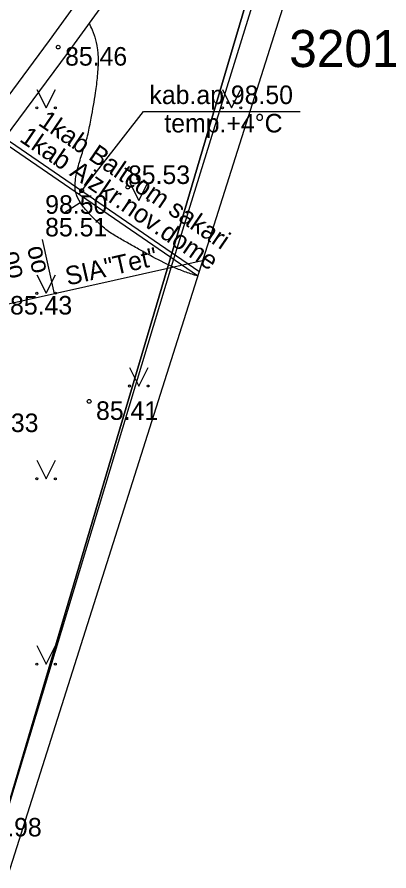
# Model space of a CAD drawing. Extents: x 576692 to 577659, y 273254 to 273799.
# Drawn here: x 576961.72 to 576971.74, y 273541.92 to 273564.95 of the extents above; entities that cross this region are included whole.
import ezdxf

# ---------------------------------------------------------------- set-up
doc = ezdxf.new("R2010")
doc.units = 0
for name, color, linetype in [('BUVE_BDET_####_####_#', 7, 'Continuous'), ('BUVE_EKAS_BPAL_####_#', 7, 'Continuous'), ('CELI_TAKA_####_####_#', 7, 'Continuous'), ('CKOM_ELEM_####_TKST_#', 7, 'Continuous'), ('ELEK_ELEM_####_####_#', 7, 'Continuous'), ('GAZE_VADP_VSP1_####_#', 7, 'Continuous'), ('GAZE_VADV_VSP1_TKST_#', 7, 'Continuous'), ('GEOD_SITP_####_TKST_#', 7, 'Continuous'), ('HIDT_REZV_####_TKST_#', 7, 'Continuous'), ('Level 62', 7, 'Continuous'), ('LKAN_ELEM_PAST_TKST_#', 7, 'Continuous'), ('POINT-ELEV', 7, 'Continuous'), ('RELJ_ELEM_####_####_#', 7, 'Continuous'), ('SILT_VADP_UDEN_####_#', 7, 'Continuous'), ('SKAN_ELEM_PAST_TKST_#', 7, 'Continuous'), ('SKAN_VADP_PAST_####_#', 7, 'Continuous')]:
    doc.layers.add(name, color=color, linetype=linetype)

msp = doc.modelspace()

# ---------------------------------------------------------------- linework, layer by layer
at = {"layer": 'BUVE_BDET_####_####_#'}
msp.add_lwpolyline([(576968.991, 273568.265), (576968.208, 273565.766), (576965.894, 273558.304), (576961.398, 273543.372), (576960.613, 273540.901), (576960.434, 273535.701), (576956.789, 273535.711), (576957.379, 273512.267)], dxfattribs=at)
at = {"layer": 'CELI_TAKA_####_####_#'}
msp.add_lwpolyline([(576875.901, 273608.92), (576873.238, 273590.115), (576867.618, 273572.942), (576871.879, 273571.462), (576866.284, 273554.628), (576861.302, 273546.668), (576863.144, 273537.44), (576882.478, 273539.149), (576882.478, 273547.068), (576949.529, 273561.695), (576947.673, 273570.204), (576952.647, 273577.562), (576971.581, 273573.757), (576961.116, 273540.729), (576960.89, 273535.214), (576957.213, 273535.221), (576957.586, 273512.35), (577020.812, 273504.477), (577024.699, 273507.761), (577034.918, 273498.457), (577056.159, 273496.649)], dxfattribs=at)
at = {"layer": 'CKOM_ELEM_####_TKST_#'}
for points in [[(576963.384, 273560.165), (576965.124, 273562.399)], [(576965.124, 273562.399), (576969.344, 273562.399)], [(576965.124, 273562.399), (576969.344, 273562.399)]]:
    msp.add_lwpolyline(points, dxfattribs=at)
at = {"layer": 'ELEK_ELEM_####_####_#'}
for points in [[(576968.001, 273571.395), (576964.942, 273567.588), (576962.585, 273564.317), (576960.191, 273561.094), (576959.596, 273560.499), (576958.425, 273559.194), (576958.097, 273558.947)], [(576968.753, 273571.373), (576965.42, 273567.224), (576963.069, 273563.963), (576960.647, 273560.7), (576960.032, 273560.087), (576959.511, 273559.505)]]:
    msp.add_lwpolyline(points, dxfattribs=at)
at = {"layer": 'GAZE_VADP_VSP1_####_#'}
msp.add_line((576962.393, 273558.954), (576962.72, 273557.49), dxfattribs=at)
at = {"layer": 'GEOD_SITP_####_TKST_#'}
msp.add_line((576963, 273559.679), (576963.422, 273559.947), dxfattribs=at)
msp.add_spline([(576966.572, 273557.971), (576966.475, 273558.001), (576966.313, 273558.054), (576965.992, 273558.178), (576965.681, 273558.324), (576965.067, 273558.65), (576964.761, 273558.823), (576964.456, 273558.997), (576964.298, 273559.092), (576964.149, 273559.196), (576964.007, 273559.311), (576963.866, 273559.441), (576963.655, 273559.656), (576963.465, 273559.884), (576963.33, 273560.126), (576963.293, 273560.254), (576963.284, 273560.319), (576963.282, 273560.385), (576963.334, 273560.786), (576963.446, 273561.19), (576963.574, 273561.595), (576963.631, 273561.798), (576963.675, 273562.002), (576963.717, 273562.227), (576963.834, 273562.907), (576963.89, 273563.362), (576963.906, 273563.588), (576963.911, 273563.701), (576963.912, 273563.814), (576963.906, 273563.964), (576963.889, 273564.113), (576963.821, 273564.403), (576963.787, 273564.499), (576963.751, 273564.594), (576963.667, 273564.777)], degree=3, dxfattribs=at)
at = {"layer": 'Level 62'}
msp.add_lwpolyline([(576958.059, 273556.448), (576966.71, 273558.382)], dxfattribs=at)
at = {"layer": 'LKAN_ELEM_PAST_TKST_#'}
for p, q in [((576962.25, 273563), (576962.5, 273562.5)), ((576962.5, 273562.5), (576962.75, 273563)), ((576967.25, 273563), (576967.5, 273562.5)), ((576967.5, 273562.5), (576967.75, 273563)), ((576964.75, 273560.5), (576965, 273560)), ((576965, 273560), (576965.25, 273560.5)), ((576962.25, 273558), (576962.5, 273557.5)), ((576962.5, 273557.5), (576962.75, 273558)), ((576964.75, 273555.5), (576965, 273555)), ((576965, 273555), (576965.25, 273555.5)), ((576962.25, 273553), (576962.5, 273552.5)), ((576962.5, 273552.5), (576962.75, 273553)), ((576962.25, 273548), (576962.5, 273547.5)), ((576962.5, 273547.5), (576962.75, 273548))]:
    msp.add_line(p, q, dxfattribs=at)
for centre, radius in [((576962.25, 273562.5), 0.028), ((576962.75, 273562.5), 0.0263), ((576967.25, 273562.5), 0.028), ((576967.75, 273562.5), 0.0263), ((576964.75, 273560), 0.028), ((576965.25, 273560), 0.0263), ((576962.25, 273557.5), 0.028), ((576962.75, 273557.5), 0.0263), ((576964.75, 273555), 0.028), ((576965.25, 273555), 0.0263), ((576962.25, 273552.5), 0.028), ((576962.75, 273552.5), 0.0263), ((576962.25, 273547.5), 0.028), ((576962.75, 273547.5), 0.0263)]:
    msp.add_circle(centre, radius, dxfattribs=at)
at = {"layer": 'RELJ_ELEM_####_####_#'}
for centre in [(576962.827, 273564.14), (576964.702, 273560.363), (576963.46, 273560.267), (576963.661, 273554.586)]:
    msp.add_circle(centre, 0.05, dxfattribs=at)
at = {"layer": 'SILT_VADP_UDEN_####_#'}
for points in [[(577033.66, 273530.686), (577031.756, 273524.733), (577028.05, 273514.57), (577024.96, 273501.23), (576972.68, 273506.2), (576954.98, 273513.09), (576956.49, 273534.78), (576960.15, 273534.54), (576960.32, 273539.8), (576969.56, 273570.99), (576978.221, 273570.568)], [(576978.221, 273570.568), (576969.56, 273570.99), (576960.32, 273539.8), (576960.15, 273534.54), (576956.49, 273534.78), (576954.98, 273513.09), (576972.68, 273506.2), (577024.96, 273501.23), (577028.05, 273514.57), (577031.756, 273524.733), (577055.384, 273496.087), (577061.73, 273507.256)]]:
    msp.add_lwpolyline(points, dxfattribs=at)
at = {"layer": 'SKAN_ELEM_PAST_TKST_#'}
msp.add_lwpolyline([(576956.433, 273565.09), (576966.62, 273558.098)], dxfattribs=at)
at = {"layer": 'SKAN_VADP_PAST_####_#'}
msp.add_line((576966.578, 273557.967), (576956.465, 273564.927), dxfattribs=at)

# ---------------------------------------------------------------- texts
at = {"layer": 'BUVE_EKAS_BPAL_####_#'}
msp.add_text('32010020152', height=1, dxfattribs=at).set_placement((576969.052, 273563.601))
at = {"layer": 'CKOM_ELEM_####_TKST_#'}
for s, p in [('kab.ap.98.50', (576965.287, 273562.603)), ('temp.+4°C', (576965.688, 273561.838))]:
    msp.add_text(s, height=0.5, dxfattribs=at).set_placement(p)
msp.add_text('1kab Aizkr.nov.dome', height=0.5, rotation=325.7163, dxfattribs=at).set_placement((576961.757, 273561.616))
at = {"layer": 'GAZE_VADP_VSP1_####_#'}
for p in [(576961.986, 273558.729), (576961.352, 273558.587)]:
    msp.add_text('oo', height=0.5, rotation=282.6046, dxfattribs=at).set_placement(p)
at = {"layer": 'GAZE_VADV_VSP1_TKST_#'}
msp.add_text('1kab Baltcom sakari', height=0.5, rotation=325.6675, dxfattribs=at).set_placement((576962.262, 273562.054))
at = {"layer": 'HIDT_REZV_####_TKST_#'}
for s, p in [(' 85.46', (576962.827, 273563.64)), (' 85.53', (576964.521, 273560.448)), (' 98.50', (576962.292, 273559.644)), (' 85.51', (576962.289, 273559.034)), (' 85.43', (576961.344, 273556.928)), (' 85.41', (576963.661, 273554.086)), (' 85.33', (576960.436, 273553.758)), (' 84.98', (576960.524, 273542.852))]:
    msp.add_text(s, height=0.5, dxfattribs=at).set_placement(p)
at = {"layer": 'POINT-ELEV'}
msp.add_text('SIA"Tet"', height=0.5, rotation=12.8347, dxfattribs=at).set_placement((576963.083, 273557.705))

doc.saveas('drawing.dxf')
